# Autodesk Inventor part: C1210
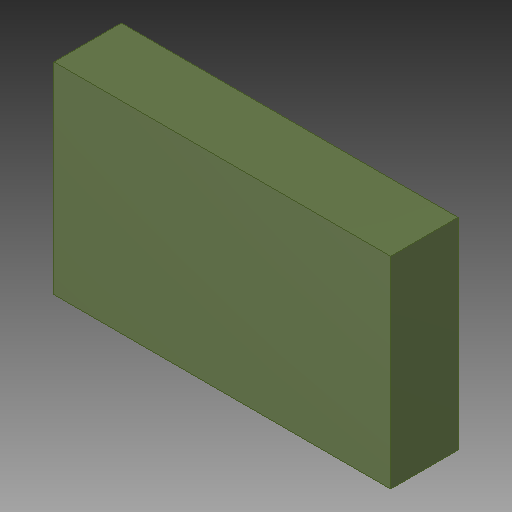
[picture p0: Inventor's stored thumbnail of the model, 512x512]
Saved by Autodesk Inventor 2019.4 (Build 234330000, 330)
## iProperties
Created: 2019-11
Part Number: C1210
Material: Generic
Document SubType Name: Modeling
Designer: Willist
Density: 1 g/cm^3
Appearance: C1210, C1210
Author: Willist
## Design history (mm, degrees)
sketch "C1210, C1210_24"
  geometry: L1 (-2.498, 1.508)-(2.498, 1.508); L2 (2.498, 1.508)-(2.498, -1.483); L3 (2.498, -1.483)-(-2.498, -1.483); L4 (-2.498, -1.483)-(-2.498, 1.508)
  constraints: 8 end point
extrude "Extrusion1" join sketch "C1210, C1210_24" distance "d0" = 1; taper "d1" = 0 deg
body "Solid1"
